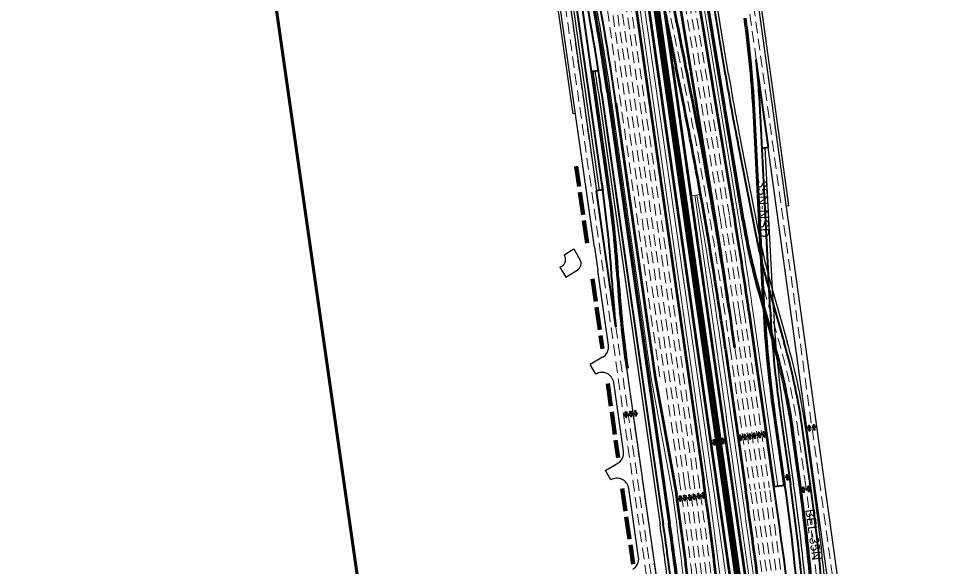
# Model space of a CAD drawing. Extents: x 2329387 to 2347382, y 6951580 to 6987999.
# Drawn here: x 2329937 to 2332250, y 6966846 to 6968230 of the extents above; entities that cross this region are included whole.
import ezdxf

# ---------------------------------------------------------------- set-up
doc = ezdxf.new("R2010")
doc.units = 0
doc.header["$LTSCALE"] = 9.6
doc.linetypes.add('LONG_DASHED', pattern=[7.5, 6, -1.5])
doc.linetypes.add('MEDIUM_DASHED', pattern=[4.5, 3, -1.5])
for name, color, linetype, lineweight in [('26', 7, 'Continuous', 53), ('27', 7, 'Continuous', 40), ('28', 7, 'Continuous', 25), ('30', 7, 'Continuous', 13), ('31', 7, 'Continuous', 53), ('41', 7, 'Continuous', 35), ('50', 7, 'MEDIUM_DASHED', 13), ('59', 7, 'LONG_DASHED', 90), ('62', 7, 'Continuous', 60)]:
    doc.layers.add(name, color=color, linetype=linetype, lineweight=lineweight)
doc.layers.add('40', color=7, linetype='Continuous')

msp = doc.modelspace()

# ---------------------------------------------------------------- linework, layer by layer
at = {"layer": '26', "lineweight": 13}
for p, q in [((2331386.358, 6969090.842), (2331675.68, 6967065.044)), ((2331752.956, 6967735.909), (2331626.312, 6968504.454)), ((2331430.614, 6968045.385), (2331534.005, 6967321.452)), ((2331790.513, 6967491.689), (2331853.855, 6967048.173)), ((2331711.657, 6967393.115), (2331762.779, 6967035.165)), ((2331534.005, 6967321.452), (2331588.27, 6967026.158))]:
    msp.add_line(p, q, dxfattribs=at)
at = {"layer": '26'}
for p, q in [((2331376.458, 6969089.428), (2331665.791, 6967063.557)), ((2331743.089, 6967734.283), (2331616.446, 6968502.828)), ((2331444.936, 6968015.834), (2331543.904, 6967322.866)), ((2331780.613, 6967490.275), (2331843.956, 6967046.759)), ((2331721.557, 6967394.529), (2331772.679, 6967036.579)), ((2331543.904, 6967322.866), (2331598.17, 6967027.572))]:
    msp.add_line(p, q, dxfattribs=at)
at = {"layer": '26', "lineweight": 13}
for centre, radius, start, end in [((2320401.269, 6965777.781), 11425.156, 8.12794, 10.11125), ((2320389.049, 6965863.345), 11517.156, 8.12795, 9.35721), ((2320321.739, 6965443.45), 11469.156, 5.00662, 8.12814), ((2309084.586, 6963796.291), 22908.312, 6.74594, 8.12795), ((2320321.739, 6965443.45), 11377.156, 5.00662, 7.99651)]:
    msp.add_arc(centre, radius, start, end, dxfattribs=at)
at = {"layer": '26'}
for centre, radius, start, end in [((2320401.269, 6965777.781), 11435.156, 8.12794, 10.10951), ((2320389.049, 6965863.345), 11507.156, 8.12795, 9.35721), ((2320321.739, 6965443.45), 11459.156, 5.00662, 8.12777), ((2309084.586, 6963796.291), 22918.312, 6.74594, 8.12795), ((2320321.739, 6965443.45), 11387.156, 5.00662, 7.99663)]:
    msp.add_arc(centre, radius, start, end, dxfattribs=at)
at = {"layer": '27', "lineweight": 25}
for p, q in [((2331403.729, 6967795.334), (2331237.088, 6968967.461)), ((2331729.38, 6968088.098), (2331625.064, 6968721.145)), ((2331763.735, 6967719.701), (2331599.398, 6968716.991)), ((2331429.47, 6967798.994), (2331387.244, 6968096.007)), ((2331400.915, 6968041.144), (2331556.468, 6966951.982)), ((2331426.741, 6968044.206), (2331582.207, 6966955.658)), ((2331816.347, 6967495.458), (2331791.899, 6967982.271)), ((2331760.587, 6967915.29), (2331805.822, 6967685.063)), ((2331842.314, 6967496.762), (2331821.938, 6967902.49)), ((2331837.631, 6967552.68), (2331877.532, 6967412.662)), ((2331804.729, 6967536.779), (2331842.91, 6967402.796)), ((2331471.567, 6967346.591), (2331475.528, 6967347.154)), ((2331841.676, 6967232.469), (2331867.715, 6967050.152)), ((2331867.415, 6967236.145), (2331893.453, 6967053.828)), ((2331908.188, 6967046.023), (2331889.341, 6967182.284)), ((2331943.848, 6967050.955), (2331925.001, 6967187.217))]:
    msp.add_line(p, q, dxfattribs=at)
at = {"layer": '27'}
for p, q in [((2331411.649, 6967796.46), (2331245.008, 6968968.587)), ((2331767.682, 6967720.351), (2331603.357, 6968717.568)), ((2331721.486, 6968086.798), (2331617.17, 6968719.844)), ((2331829.87, 6967903.587), (2331799.148, 6968125.702)), ((2331400.679, 6968097.419), (2331383.353, 6968094.955)), ((2331408.922, 6968041.661), (2331564.387, 6966953.113)), ((2331422.782, 6968043.641), (2331578.247, 6966955.093)), ((2331820.342, 6967495.659), (2331795.894, 6967982.471)), ((2331834.324, 6967496.361), (2331809.876, 6967983.173)), ((2331752.737, 6967913.748), (2331797.972, 6967683.521)), ((2331829.87, 6967903.587), (2331814.006, 6967901.393)), ((2331411.649, 6967796.46), (2331395.809, 6967794.208)), ((2331408.734, 6967816.964), (2331411.649, 6967796.46)), ((2331444.619, 6967450.882), (2331395.809, 6967794.208)), ((2331829.937, 6967550.488), (2331869.838, 6967410.469)), ((2331808.575, 6967537.876), (2331846.757, 6967403.892)), ((2331845.636, 6967233.035), (2331871.674, 6967050.718)), ((2331859.495, 6967235.014), (2331885.534, 6967052.697)), ((2331909.378, 6967066.616), (2331893.303, 6967182.832)), ((2331935.924, 6967049.859), (2331917.077, 6967186.121)), ((2331871.674, 6967050.718), (2331843.949, 6967046.806))]:
    msp.add_line(p, q, dxfattribs=at)
msp.add_lwpolyline([(2331425.511, 6967798.421), (2331383.284, 6968095.444), (2331323.287, 6968517.451)], dxfattribs=at)
for centre, radius, start, end in [((2325738.879, 6967231.872), 5727.578, 8.12795, 11.67456), ((2325738.879, 6967231.872), 5741.578, 8.12795, 11.67456), ((2325772.912, 6967205.762), 5729.578, 8.12795, 11.83684), ((2328948.693, 6967839.484), 2850.789, 2.87499, 7.87499), ((2328948.693, 6967839.484), 2864.789, 2.87499, 5.73392), ((2337374.824, 6969018.375), 5729.578, 189.35732, 191.11587), ((2328575.381, 6967393.227), 2864.789, 3.5487, 8.09153), ((2328575.381, 6967393.227), 2878.789, 3.5487, 8.09153), ((2333382.922, 6967986.516), 1637.023, 189.35731, 195.90594), ((2333404.282, 6967999.128), 1637.022, 191.11588, 195.90594), ((2334293.973, 6967747.871), 2864.789, 183.5487, 185.95046), ((2334293.973, 6967747.871), 2850.789, 183.5487, 188.09189), ((2339406.145, 6959556.474), 7976, 170.51466, 170.51466), ((2334695.507, 6967640.05), 2878.789, 182.87499, 188.12795), ((2334695.507, 6967640.05), 2864.789, 182.87499, 188.12795), ((2330295.493, 6966961.829), 1613.022, 7.87501, 15.90594), ((2330295.493, 6966961.829), 1637.022, 7.87501, 15.90594), ((2326225.909, 6966280.498), 5737.578, 1.61382, 7.87499), ((2309084.586, 6963796.291), 22990.312, 6.74594, 8.12795), ((2326213.511, 6966242.625), 5715.578, 1.82199, 8.12795), ((2326213.511, 6966242.625), 5729.578, 1.82199, 8.12795), ((2326260.379, 6966264.837), 5729.578, 4.84688, 7.87499), ((2320220.341, 6965332.97), 11459.156, 6.84922, 8.12795), ((2320220.341, 6965332.97), 11473.156, 6.84922, 8.12795)]:
    msp.add_arc(centre, radius, start, end, dxfattribs=at)
at = {"layer": '27', "lineweight": 25}
for centre, radius, start, end in [((2325738.879, 6967231.872), 5745.578, 8.12795, 11.67456), ((2325758.591, 6967235.313), 5729.578, 8.12795, 11.51824), ((2328948.693, 6967839.484), 2846.789, 2.87499, 7.87499), ((2325758.591, 6967235.313), 5699.578, 8.12795, 8.69229), ((2337374.824, 6969018.375), 5721.578, 189.35732, 191.11587), ((2328575.381, 6967393.227), 2882.789, 3.5487, 8.09153), ((2333382.922, 6967986.516), 1641.023, 189.35731, 195.90594), ((2333404.282, 6967999.128), 1629.022, 191.11588, 195.90594), ((2334293.973, 6967747.871), 2846.789, 183.5487, 188.09189), ((2334695.507, 6967640.05), 2882.789, 182.87499, 188.12795), ((2334695.507, 6967640.05), 2856.789, 182.87499, 188.12795), ((2330295.493, 6966961.829), 1609.022, 7.87501, 15.90594), ((2330295.493, 6966961.829), 1645.022, 7.87501, 15.90594), ((2326225.909, 6966280.498), 5733.578, 1.61382, 7.87499), ((2326213.511, 6966242.625), 5737.578, 1.82199, 8.12795), ((2326260.379, 6966264.837), 5737.578, 4.84688, 7.87499), ((2320220.341, 6965332.97), 11451.156, 6.84922, 8.12795), ((2320220.341, 6965332.97), 11477.156, 6.84922, 8.12795)]:
    msp.add_arc(centre, radius, start, end, dxfattribs=at)
at = {"layer": '28'}
for p, q in [((2331390.789, 6967651.904), (2331040.416, 6970116.36)), ((2331396.799, 6967794.349), (2331171.328, 6969380.268)), ((2332078.029, 6966291.919), (2331740.454, 6968732.516)), ((2331881.451, 6967756.928), (2331746.397, 6968733.338)), ((2332123.879, 6965770.67), (2331828.88, 6967903.45)), ((2331875.507, 6967756.106), (2331881.451, 6967756.928)), ((2331314.492, 6967632.857), (2331338.858, 6967647.438)), ((2331338.858, 6967647.438), (2331354.265, 6967621.117)), ((2331390.789, 6967651.904), (2331399.093, 6967593.494)), ((2331314.492, 6967632.857), (2331315.364, 6967631.368)), ((2331303.753, 6967601.359), (2331308.312, 6967604.066)), ((2331303.753, 6967601.359), (2331318.213, 6967576.602)), ((2331318.213, 6967576.602), (2331347.213, 6967593.815)), ((2331425.991, 6967404.298), (2331399.093, 6967593.494)), ((2331411.468, 6967374.199), (2331380.163, 6967355.837)), ((2331394.416, 6967331.721), (2331380.163, 6967355.837)), ((2331662.241, 6966012.534), (2331472.552, 6967346.767)), ((2331464.032, 6967136.726), (2331439.381, 6967310.117)), ((2331418.616, 6967088.601), (2331449.45, 6967106.592)), ((2331432.526, 6967064.763), (2331418.616, 6967088.601)), ((2331502.09, 6966869.035), (2331477.346, 6967043.074))]:
    msp.add_line(p, q, dxfattribs=at)
msp.add_lwpolyline([(2331342.848, 6967989.112), (2331336.908, 6967988.268), (2331196.027, 6968979.198)], dxfattribs=at)
for centre, radius, start, end in [((2331298.104, 6967621.264), 20, 300.69096, 30.34277), ((2331337.005, 6967611.013), 20, 300.69096, 30.34277), ((2331396.29, 6967400.076), 30, 300.39394, 8.09153), ((2331409.679, 6967305.894), 30, 8.09153, 120.58346), ((2331434.33, 6967132.503), 30, 300.26364, 8.09153), ((2331447.645, 6967038.851), 30, 8.09153, 120.26364), ((2331472.388, 6966864.812), 30, 300.22184, 8.09153)]:
    msp.add_arc(centre, radius, start, end, dxfattribs=at)
at = {"layer": '30', "lineweight": 53}
msp.add_line((2331695.724, 6967726.499), (2331569.084, 6968495.023), dxfattribs=at)
for centre, radius, start, end in [((2342838.628, 6970448.32), 11459.156, 188.12796, 191.75872), ((2342838.628, 6970448.32), 11483.156, 190.95749, 191.75872), ((2320401.269, 6965777.781), 11435.156, 10.10951, 11.75872), ((2320401.269, 6965777.781), 11459.156, 8.12795, 11.75872), ((2320389.049, 6965863.345), 11459.156, 8.12795, 9.35731)]:
    msp.add_arc(centre, radius, start, end, dxfattribs=at)
at = {"layer": '31'}
for p, q in [((2331296.241, 6969976.458), (2331690.26, 6967217.584)), ((2331333.019, 6969619.916), (2331676.4, 6967215.605)), ((2331470.826, 6968824.761), (2331700.159, 6967218.998)), ((2331564.828, 6968265.595), (2331714.019, 6967220.977)), ((2331690.26, 6967217.584), (2331941.267, 6965460.063)), ((2331700.159, 6967218.998), (2331951.166, 6965461.481)), ((2331714.019, 6967220.977), (2331965.025, 6965463.46)), ((2331676.4, 6967215.605), (2331927.407, 6965458.088))]:
    msp.add_line(p, q, dxfattribs=at)
at = {"layer": '31', "lineweight": 13}
for p, q in [((2331300.2, 6969977.023), (2331694.22, 6967218.149)), ((2331355.421, 6969392.336), (2331666.501, 6967214.191)), ((2331466.866, 6968824.195), (2331696.2, 6967218.432)), ((2331578.657, 6968041.452), (2331696.2, 6967218.432)), ((2331633.974, 6967781.439), (2331658.883, 6967784.997)), ((2331643.874, 6967782.853), (2331723.918, 6967222.391)), ((2331658.883, 6967784.997), (2331660.077, 6967785.167)), ((2331694.22, 6967218.149), (2331945.226, 6965460.633)), ((2331696.2, 6967218.432), (2331947.206, 6965460.916)), ((2331723.658, 6967224.211), (2331974.925, 6965464.874)), ((2331666.501, 6967214.191), (2331917.507, 6965456.674))]:
    msp.add_line(p, q, dxfattribs=at)
at = {"layer": '41'}
for points in [[(2331470.85, 6967236.195), (2331467.875, 6967235.797), (2331468.778, 6967229.05), (2331466.362, 6967228.727), (2331471.062, 6967222.092), (2331473.853, 6967229.729), (2331471.752, 6967229.448)], [(2331483.085, 6967237.988), (2331480.11, 6967237.59), (2331481.013, 6967230.844), (2331478.597, 6967230.52), (2331483.297, 6967223.885), (2331486.088, 6967231.522), (2331483.987, 6967231.241)], [(2331495.44, 6967239.499), (2331492.466, 6967239.101), (2331493.368, 6967232.354), (2331490.953, 6967232.031), (2331495.653, 6967225.396), (2331498.444, 6967233.033), (2331496.343, 6967232.752)], [(2331932.239, 6967188.428), (2331935.215, 6967188.818), (2331934.331, 6967195.567), (2331936.747, 6967195.884), (2331932.065, 6967202.532), (2331929.254, 6967194.902), (2331931.355, 6967195.177)], [(2331944.332, 6967190.188), (2331947.307, 6967190.578), (2331946.423, 6967197.327), (2331948.84, 6967197.644), (2331944.158, 6967204.292), (2331941.346, 6967196.662), (2331943.448, 6967196.937)], [(2331758.659, 6967163.995), (2331761.621, 6967164.474), (2331760.536, 6967171.194), (2331762.942, 6967171.582), (2331758.063, 6967178.088), (2331755.481, 6967170.377), (2331757.573, 6967170.715)], [(2331770.528, 6967165.759), (2331773.491, 6967166.238), (2331772.405, 6967172.957), (2331774.811, 6967173.346), (2331769.933, 6967179.852), (2331767.351, 6967172.141), (2331769.443, 6967172.479)], [(2331782.398, 6967167.523), (2331785.36, 6967168.002), (2331784.275, 6967174.721), (2331786.681, 6967175.11), (2331781.802, 6967181.615), (2331779.22, 6967173.905), (2331781.313, 6967174.243)], [(2331794.268, 6967169.287), (2331797.23, 6967169.766), (2331796.145, 6967176.485), (2331798.551, 6967176.874), (2331793.672, 6967183.379), (2331791.09, 6967175.669), (2331793.182, 6967176.007)], [(2331806.137, 6967171.051), (2331809.1, 6967171.529), (2331808.014, 6967178.249), (2331810.42, 6967178.638), (2331805.542, 6967185.143), (2331802.96, 6967177.432), (2331805.052, 6967177.77)], [(2331818.007, 6967172.815), (2331820.969, 6967173.293), (2331819.884, 6967180.013), (2331822.29, 6967180.401), (2331817.411, 6967186.907), (2331814.829, 6967179.196), (2331816.922, 6967179.534)], [(2331693.518, 6967166.472), (2331690.546, 6967166.059), (2331691.482, 6967159.317), (2331689.068, 6967158.982), (2331693.802, 6967152.37), (2331696.554, 6967160.022), (2331694.455, 6967159.73)], [(2331714.364, 6967155.971), (2331717.336, 6967156.384), (2331716.399, 6967163.126), (2331718.813, 6967163.461), (2331714.08, 6967170.073), (2331711.328, 6967162.421), (2331713.427, 6967162.713)], [(2331876.799, 6967064.471), (2331879.764, 6967064.933), (2331878.716, 6967071.659), (2331881.125, 6967072.034), (2331876.283, 6967078.567), (2331873.657, 6967070.871), (2331875.751, 6967071.197)], [(2331665.643, 6967032.316), (2331662.671, 6967031.903), (2331663.607, 6967025.161), (2331661.193, 6967024.826), (2331665.927, 6967018.214), (2331668.679, 6967025.866), (2331666.579, 6967025.574)], [(2331917.472, 6967032.925), (2331920.447, 6967033.315), (2331919.563, 6967040.064), (2331921.98, 6967040.38), (2331917.298, 6967047.029), (2331914.486, 6967039.399), (2331916.588, 6967039.674)], [(2331930.442, 6967034.914), (2331933.417, 6967035.303), (2331932.533, 6967042.052), (2331934.95, 6967042.369), (2331930.268, 6967049.017), (2331927.456, 6967041.387), (2331929.558, 6967041.663)], [(2331607.804, 6967024.242), (2331604.832, 6967023.829), (2331605.769, 6967017.087), (2331603.354, 6967016.752), (2331608.088, 6967010.14), (2331610.84, 6967017.792), (2331608.741, 6967017.5)], [(2331618.927, 6967025.862), (2331615.955, 6967025.449), (2331616.891, 6967018.707), (2331614.477, 6967018.372), (2331619.211, 6967011.76), (2331621.963, 6967019.412), (2331619.864, 6967019.12)], [(2331631.689, 6967027.104), (2331628.717, 6967026.691), (2331629.654, 6967019.949), (2331627.239, 6967019.614), (2331631.973, 6967013.002), (2331634.725, 6967020.654), (2331632.626, 6967020.362)], [(2331642.812, 6967028.724), (2331639.84, 6967028.311), (2331640.776, 6967021.569), (2331638.362, 6967021.234), (2331643.096, 6967014.622), (2331645.848, 6967022.273), (2331643.749, 6967021.982)], [(2331654.52, 6967030.697), (2331651.548, 6967030.284), (2331652.484, 6967023.542), (2331650.07, 6967023.206), (2331654.804, 6967016.595), (2331657.556, 6967024.246), (2331655.457, 6967023.955)]]:
    msp.add_lwpolyline(points, close=True, dxfattribs=at)
at = {"layer": '50'}
for p, q in [((2330631.386, 6973881.958), (2331606.386, 6967055.128)), ((2330643.265, 6973883.655), (2331618.272, 6967056.781)), ((2330655.145, 6973885.352), (2331630.147, 6967058.504)), ((2331637.49, 6966009.015), (2330956.52, 6970798.829)), ((2331395.809, 6967794.208), (2331170.338, 6969380.127)), ((2331352.7, 6969086.035), (2331642.032, 6967060.168)), ((2331364.579, 6969087.731), (2331653.902, 6967061.926)), ((2331799.148, 6968125.702), (2331715.689, 6968729.091)), ((2332198.633, 6965325.094), (2331727.576, 6968730.735)), ((2331707.565, 6967728.45), (2331580.925, 6968496.975)), ((2331719.405, 6967730.401), (2331592.765, 6968498.926)), ((2331731.245, 6967732.353), (2331604.605, 6968500.877)), ((2331411.345, 6968335.905), (2331555.784, 6967324.562)), ((2331818.396, 6967547.199), (2331858.297, 6967407.18)), ((2331744.975, 6967485.185), (2331808.317, 6967041.669)), ((2331756.854, 6967486.882), (2331820.197, 6967043.366)), ((2331768.734, 6967488.578), (2331832.076, 6967045.062)), ((2331649.37, 6966010.704), (2331444.619, 6967450.882)), ((2331733.436, 6967396.225), (2331784.558, 6967038.276)), ((2331745.315, 6967397.925), (2331796.438, 6967039.972)), ((2331661.251, 6966012.393), (2331471.562, 6967346.626)), ((2331924.037, 6967048.215), (2331905.19, 6967184.476))]:
    msp.add_line(p, q, dxfattribs=at)
for centre, radius, start, end in [((2342838.628, 6970448.32), 11471.156, 188.12796, 191.75872), ((2320401.269, 6965777.781), 11447.156, 8.12794, 11.75872), ((2320389.049, 6965863.345), 11471.156, 8.12795, 9.35731), ((2320389.049, 6965863.345), 11483.156, 8.12795, 9.35731), ((2320389.049, 6965863.345), 11495.156, 8.12795, 9.35731), ((2333404.282, 6967999.128), 1649.022, 195.90594, 195.90595), ((2330295.493, 6966961.829), 1625.022, 7.87501, 15.90594), ((2320321.739, 6965443.45), 11399.156, 5.00662, 8.12804), ((2320321.739, 6965443.45), 11411.156, 5.00662, 8.12782), ((2320321.739, 6965443.45), 11423.156, 5.00662, 8.12795), ((2320321.739, 6965443.45), 11435.156, 5.00662, 8.12779), ((2320321.739, 6965443.45), 11447.156, 5.00662, 8.1281), ((2309084.586, 6963796.291), 22930.312, 6.74594, 8.12795), ((2309084.586, 6963796.291), 22942.312, 6.74594, 8.12795), ((2309084.586, 6963796.291), 22954.312, 6.74594, 8.12795), ((2309084.586, 6963796.291), 22966.312, 6.74594, 8.12795), ((2309084.586, 6963796.291), 22978.312, 6.74594, 8.12795), ((2326260.379, 6966264.837), 5717.578, 3.86462, 7.87499)]:
    msp.add_arc(centre, radius, start, end, dxfattribs=at)
at = {"layer": '59'}
for p, q in [((2331372.372, 6967662.472), (2331344.827, 6967856.104)), ((2331386.134, 6967571.963), (2331411.063, 6967395.51)), ((2331424.445, 6967307.879), (2331450.502, 6967120.204)), ((2331460.925, 6967042.992), (2331488.47, 6966852.339))]:
    msp.add_line(p, q, dxfattribs=at)
at = {"layer": '62'}
msp.add_lwpolyline([(2329936.564, 6972812.843), (2331011.084, 6965289.186), (2332891.999, 6965557.816), (2331817.479, 6973081.473)], close=True, dxfattribs=at)

# ---------------------------------------------------------------- texts
at = {"layer": '40', "width": 1.05}
msp.add_text('35N-NSD', height=24, rotation=272.767, dxfattribs=at).set_placement((2331801.558, 6967819.387))
at = {"layer": '40'}
msp.add_text('BEL-35N', height=24, rotation=277.941, dxfattribs=at).set_placement((2331922.865, 6966989.358))

doc.saveas('drawing.dxf')
